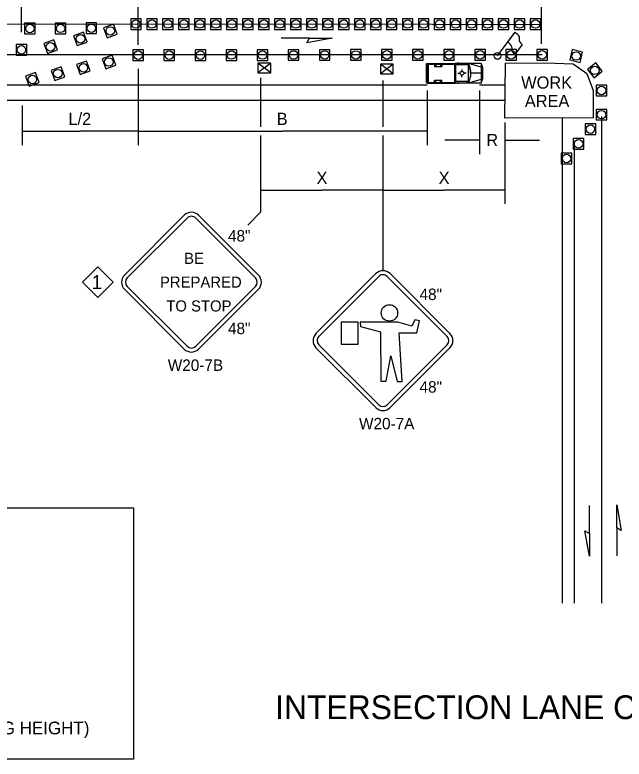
# Model space of a CAD drawing. Extents: x 99988 to 100172, y 99995 to 100047.
# Drawn here: x 100003.104 to 100006.942, y 100001.199 to 100005.887 of the extents above; entities that cross this region are included whole.
import ezdxf

# ---------------------------------------------------------------- set-up
doc = ezdxf.new("R2010")
doc.units = 0
for name, color, linetype in [('Default', 7, 'Continuous'), ('Level 15', 7, 'Continuous'), ('Level 20', 7, 'Continuous'), ('SH_DE_DetailBody1Text', 7, 'Continuous'), ('SH_DE_DetailHeading1Text', 7, 'Continuous'), ('SH_GI_TrafficMvmntArrowRt1Lane', 7, 'Continuous'), ('SH_TI_SignSpacing35to70Note', 7, 'Continuous'), ('TR_SN_WarningSigns', 7, 'Continuous'), ('TR_WZ_FlaggingStation', 7, 'Continuous'), ('TR_WZ_TrafficSafetyCone', 7, 'Continuous'), ('TR_WZ_TruckBuffer', 7, 'Continuous'), ('TR_WZ_WorkZoneDetails', 7, 'Continuous')]:
    doc.layers.add(name, color=color, linetype=linetype)

msp = doc.modelspace()

# ---------------------------------------------------------------- linework, layer by layer
at = {"layer": 'Default'}
for p, q in [((100005.7349, 100005.8272), (100001.0926, 100005.8307)), ((100005.7349, 100005.8272), (100006.4173, 100005.8296)), ((100004.7155, 100005.5226), (100004.6357, 100005.5824)), ((100004.7155, 100005.5824), (100004.6357, 100005.5226)), ((100004.6756, 100005.5525), (100004.6756, 100005.5525)), ((100004.6758, 100005.5524), (100004.6758, 100005.5524)), ((100005.4879, 100005.5169), (100005.4081, 100005.5767)), ((100005.4879, 100005.5767), (100005.4081, 100005.5169)), ((100005.448, 100005.5468), (100005.448, 100005.5468)), ((100005.4482, 100005.5467), (100005.4482, 100005.5467))]:
    msp.add_line(p, q, dxfattribs=at)
for points in [[(100004.7155, 100005.5226), (100004.7155, 100005.5824), (100004.6357, 100005.5824), (100004.6357, 100005.5226)], [(100005.4879, 100005.5169), (100005.4879, 100005.5767), (100005.4081, 100005.5767), (100005.4081, 100005.5169)], [(100006.1943, 100005.5829), (100006.4462, 100005.5845), (100006.6221, 100005.5781), (100006.7076, 100005.5179), (100006.7472, 100005.4101), (100006.7472, 100005.239), (100006.1896, 100005.2358)]]:
    msp.add_lwpolyline(points, close=True, dxfattribs=at)
at = {"layer": 'Level 15'}
for p, q in [((100003.1499, 100005.1555), (100003.515, 100005.1555)), ((100003.88, 100005.1555), (100003.515, 100005.1555)), ((100003.88, 100005.1555), (100004.7908, 100005.1555)), ((100005.7015, 100005.1555), (100004.7908, 100005.1555)), ((100006.032, 100005.0989), (100005.812, 100005.0989)), ((100006.19, 100005.0989), (100006.41, 100005.0989)), ((100004.6514, 100004.7836), (100005.0371, 100004.7836)), ((100005.4228, 100004.7836), (100005.0371, 100004.7836)), ((100005.4228, 100004.7836), (100005.8064, 100004.7836)), ((100006.19, 100004.7836), (100005.8064, 100004.7836))]:
    msp.add_line(p, q, dxfattribs=at)
at = {"layer": 'SH_DE_DetailBody1Text'}
msp.add_lwpolyline([(100003.6269, 100004.3002), (100003.7234, 100004.2037), (100003.6269, 100004.1071), (100003.5303, 100004.2037)], close=True, dxfattribs=at)
at = {"layer": 'SH_GI_TrafficMvmntArrowRt1Lane'}
for p, q in [((100004.9592, 100005.7403), (100004.7824, 100005.7403)), ((100006.7234, 100002.6206), (100006.7234, 100002.7974)), ((100006.8951, 100002.656), (100006.8951, 100002.4792))]:
    msp.add_line(p, q, dxfattribs=at)
for points in [[(100005.1034, 100005.7403), (100004.9429, 100005.712), (100004.9592, 100005.7403)], [(100006.8951, 100002.8001), (100006.9234, 100002.6396), (100006.8951, 100002.656)], [(100006.7234, 100002.4765), (100006.6951, 100002.6369), (100006.7234, 100002.6206)]]:
    msp.add_lwpolyline(points, close=True, dxfattribs=at)
at = {"layer": 'SH_TI_SignSpacing35to70Note'}
msp.add_lwpolyline([(100000.1818, 100002.782), (100003.8506, 100002.782), (100003.8506, 100001.1987), (100000.1818, 100001.1987)], close=True, dxfattribs=at)
at = {"layer": 'TR_SN_WarningSigns'}
for p, q in [((100003.7944, 100004.2485), (100004.1714, 100004.6255)), ((100004.2611, 100004.6255), (100004.638, 100004.2485)), ((100003.8124, 100004.2306), (100004.1893, 100004.6075)), ((100004.2432, 100004.6075), (100004.6201, 100004.2306)), ((100005.001, 100003.8802), (100005.3779, 100004.2572)), ((100005.0189, 100003.8623), (100005.3959, 100004.2392)), ((100005.4497, 100004.2392), (100005.8267, 100003.8623)), ((100005.4677, 100004.2572), (100005.8446, 100003.8802)), ((100004.1714, 100003.7819), (100003.7944, 100004.1588)), ((100004.1893, 100003.7998), (100003.8124, 100004.1767)), ((100004.6201, 100004.1767), (100004.2431, 100003.7998)), ((100004.638, 100004.1588), (100004.2611, 100003.7819)), ((100005.3779, 100003.4135), (100005.001, 100003.7905)), ((100005.3959, 100003.4315), (100005.0189, 100003.8084)), ((100005.8267, 100003.8084), (100005.4497, 100003.4315)), ((100005.8446, 100003.7905), (100005.4677, 100003.4135))]:
    msp.add_line(p, q, dxfattribs=at)
for points in [[(100005.2799, 100003.9511), (100005.2815, 100003.9246), (100005.4068, 100003.8917), (100005.4095, 100003.5789), (100005.4421, 100003.5789), (100005.4731, 100003.74), (100005.5122, 100003.5785), (100005.5437, 100003.5785), (100005.5258, 100003.8854), (100005.637, 100003.8854), (100005.6521, 100003.9599), (100005.6239, 100003.9653), (100005.6058, 100003.9272), (100005.5173, 100003.9511)], [(100005.1603, 100003.9508), (100005.1603, 100003.8136), (100005.2673, 100003.8136), (100005.2673, 100003.9508)]]:
    msp.add_lwpolyline(points, close=True, dxfattribs=at)
msp.add_circle((100005.4636, 100004.0099), 0.0519, dxfattribs=at)
for centre, radius, start, end in [((100004.2162, 100004.5806), 0.0635, 44.9963, 134.9997), ((100004.2162, 100004.5806), 0.0381, 44.9963, 134.9997), ((100003.8393, 100004.2037), 0.0635, 134.9966, 224.9936), ((100004.5932, 100004.2037), 0.0635, 314.9994, 44.9948), ((100005.4228, 100004.2123), 0.0635, 44.9963, 134.9997), ((100005.4228, 100004.2123), 0.0381, 44.9963, 134.9997), ((100003.8393, 100004.2037), 0.0381, 134.9966, 224.9936), ((100004.5932, 100004.2037), 0.0381, 314.9994, 44.9948), ((100005.0458, 100003.8354), 0.0635, 134.9966, 224.9936), ((100005.0458, 100003.8354), 0.0381, 134.9966, 224.9936), ((100005.7997, 100003.8353), 0.0381, 314.9994, 44.9948), ((100005.7997, 100003.8353), 0.0635, 314.9994, 44.9948), ((100004.2162, 100003.8267), 0.0635, 225, 314.9996), ((100004.2162, 100003.8267), 0.0381, 225, 314.9996), ((100005.4228, 100003.4584), 0.0635, 225, 314.9996), ((100005.4228, 100003.4584), 0.0381, 225, 314.9996)]:
    msp.add_arc(centre, radius, start, end, dxfattribs=at)
at = {"layer": 'TR_WZ_FlaggingStation'}
for p, q in [((100006.1445, 100005.629), (100006.2555, 100005.779)), ((100006.2104, 100005.7181), (100006.2556, 100005.7791)), ((100006.2104, 100005.7181), (100006.2104, 100005.7181)), ((100006.3007, 100005.7014), (100006.2544, 100005.6389))]:
    msp.add_line(p, q, dxfattribs=at)
for points in [[(100006.2556, 100005.7791), (100006.2585, 100005.7765), (100006.2676, 100005.7687), (100006.2741, 100005.7617), (100006.2776, 100005.755), (100006.2809, 100005.7495), (100006.2819, 100005.7438), (100006.2817, 100005.7379), (100006.28, 100005.7342), (100006.28, 100005.7271), (100006.2838, 100005.7193), (100006.2891, 100005.7122), (100006.3007, 100005.7014)], [(100006.2544, 100005.6389), (100006.2502, 100005.6424), (100006.2416, 100005.6508), (100006.2361, 100005.662), (100006.2359, 100005.6702), (100006.2371, 100005.6774), (100006.2355, 100005.6866), (100006.2313, 100005.6938), (100006.2237, 100005.7035), (100006.2104, 100005.7181)]]:
    msp.add_lwpolyline(points, dxfattribs=at)
msp.add_circle((100006.1445, 100005.629), 0.0214, dxfattribs=at)
at = {"layer": 'TR_WZ_TrafficSafetyCone'}
for points in [[(100003.1656, 100005.7682), (100003.2324, 100005.7682), (100003.2324, 100005.835), (100003.1656, 100005.835)], [(100003.359, 100005.769), (100003.4258, 100005.769), (100003.4258, 100005.8358), (100003.359, 100005.8358)], [(100003.5524, 100005.7698), (100003.6193, 100005.7698), (100003.6193, 100005.8366), (100003.5524, 100005.8366)], [(100003.8337, 100005.7962), (100003.9005, 100005.7962), (100003.9005, 100005.863), (100003.8337, 100005.863)], [(100003.9344, 100005.7962), (100004.0012, 100005.7962), (100004.0012, 100005.863), (100003.9344, 100005.863)], [(100004.0351, 100005.7962), (100004.1019, 100005.7962), (100004.1019, 100005.863), (100004.0351, 100005.863)], [(100004.1357, 100005.7962), (100004.2026, 100005.7962), (100004.2026, 100005.863), (100004.1357, 100005.863)], [(100004.2364, 100005.7962), (100004.3032, 100005.7962), (100004.3032, 100005.863), (100004.2364, 100005.863)], [(100004.3371, 100005.7962), (100004.4039, 100005.7962), (100004.4039, 100005.863), (100004.3371, 100005.863)], [(100004.4378, 100005.7962), (100004.5046, 100005.7962), (100004.5046, 100005.863), (100004.4378, 100005.863)], [(100004.5384, 100005.7962), (100004.6052, 100005.7962), (100004.6052, 100005.863), (100004.5384, 100005.863)], [(100004.6391, 100005.7962), (100004.7059, 100005.7962), (100004.7059, 100005.863), (100004.6391, 100005.863)], [(100004.7398, 100005.7962), (100004.8066, 100005.7962), (100004.8066, 100005.863), (100004.7398, 100005.863)], [(100004.8404, 100005.7962), (100004.9072, 100005.7962), (100004.9072, 100005.863), (100004.8404, 100005.863)], [(100004.9411, 100005.7962), (100005.0079, 100005.7962), (100005.0079, 100005.863), (100004.9411, 100005.863)], [(100005.0418, 100005.7962), (100005.1086, 100005.7962), (100005.1086, 100005.863), (100005.0418, 100005.863)], [(100005.1424, 100005.7962), (100005.2092, 100005.7962), (100005.2092, 100005.863), (100005.1424, 100005.863)], [(100005.2431, 100005.7962), (100005.3099, 100005.7962), (100005.3099, 100005.863), (100005.2431, 100005.863)], [(100005.3438, 100005.7962), (100005.4106, 100005.7962), (100005.4106, 100005.863), (100005.3438, 100005.863)], [(100005.4444, 100005.7962), (100005.5113, 100005.7962), (100005.5113, 100005.863), (100005.4444, 100005.863)], [(100005.5451, 100005.7962), (100005.6119, 100005.7962), (100005.6119, 100005.863), (100005.5451, 100005.863)], [(100005.6458, 100005.7962), (100005.7126, 100005.7962), (100005.7126, 100005.863), (100005.6458, 100005.863)], [(100005.7465, 100005.7962), (100005.8133, 100005.7962), (100005.8133, 100005.863), (100005.7465, 100005.863)], [(100005.8471, 100005.7962), (100005.9139, 100005.7962), (100005.9139, 100005.863), (100005.8471, 100005.863)], [(100005.9478, 100005.7962), (100006.0146, 100005.7962), (100006.0146, 100005.863), (100005.9478, 100005.863)], [(100006.0485, 100005.7962), (100006.1153, 100005.7962), (100006.1153, 100005.863), (100006.0485, 100005.863)], [(100006.1491, 100005.7962), (100006.2159, 100005.7962), (100006.2159, 100005.863), (100006.1491, 100005.863)], [(100006.2498, 100005.7962), (100006.3166, 100005.7962), (100006.3166, 100005.863), (100006.2498, 100005.863)], [(100006.3505, 100005.7962), (100006.4173, 100005.7962), (100006.4173, 100005.863), (100006.3505, 100005.863)], [(100003.6854, 100005.7436), (100003.7482, 100005.7665), (100003.7254, 100005.8292), (100003.6626, 100005.8064)], [(100003.4972, 100005.6937), (100003.5599, 100005.7165), (100003.5371, 100005.7793), (100003.4743, 100005.7565)], [(100003.1117, 100005.6342), (100003.1785, 100005.6342), (100003.1785, 100005.701), (100003.1117, 100005.701)], [(100003.3089, 100005.6438), (100003.3717, 100005.6666), (100003.3488, 100005.7294), (100003.286, 100005.7066)], [(100003.8478, 100005.6003), (100003.9146, 100005.6003), (100003.9146, 100005.6671), (100003.8478, 100005.6671)], [(100004.0435, 100005.6005), (100004.1104, 100005.6005), (100004.1104, 100005.6673), (100004.0435, 100005.6673)], [(100004.2393, 100005.6007), (100004.3061, 100005.6007), (100004.3061, 100005.6675), (100004.2393, 100005.6675)], [(100004.4351, 100005.6009), (100004.5019, 100005.6009), (100004.5019, 100005.6677), (100004.4351, 100005.6677)], [(100004.6309, 100005.6011), (100004.6977, 100005.6011), (100004.6977, 100005.6679), (100004.6309, 100005.6679)], [(100004.8266, 100005.6013), (100004.8934, 100005.6013), (100004.8934, 100005.6681), (100004.8266, 100005.6681)], [(100005.0224, 100005.6015), (100005.0892, 100005.6015), (100005.0892, 100005.6683), (100005.0224, 100005.6683)], [(100005.2182, 100005.6017), (100005.285, 100005.6017), (100005.285, 100005.6685), (100005.2182, 100005.6685)], [(100005.414, 100005.6019), (100005.4808, 100005.6019), (100005.4808, 100005.6687), (100005.414, 100005.6687)], [(100005.6097, 100005.6021), (100005.6765, 100005.6021), (100005.6765, 100005.6689), (100005.6097, 100005.6689)], [(100005.8055, 100005.6023), (100005.8723, 100005.6023), (100005.8723, 100005.6691), (100005.8055, 100005.6691)], [(100006.0013, 100005.6025), (100006.0681, 100005.6025), (100006.0681, 100005.6693), (100006.0013, 100005.6693)], [(100006.197, 100005.6027), (100006.2639, 100005.6027), (100006.2639, 100005.6695), (100006.197, 100005.6695)], [(100006.3928, 100005.6029), (100006.4596, 100005.6029), (100006.4596, 100005.6697), (100006.3928, 100005.6697)], [(100006.5994, 100005.6036), (100006.6643, 100005.5881), (100006.6798, 100005.6531), (100006.6149, 100005.6686)], [(100003.5157, 100005.5111), (100003.5785, 100005.534), (100003.5557, 100005.5968), (100003.4929, 100005.5739)], [(100003.6763, 100005.5477), (100003.7391, 100005.5706), (100003.7163, 100005.6334), (100003.6535, 100005.6105)], [(100003.3551, 100005.4746), (100003.4179, 100005.4974), (100003.3951, 100005.5602), (100003.3323, 100005.5373)], [(100006.7109, 100005.5434), (100006.7524, 100005.4911), (100006.8048, 100005.5326), (100006.7632, 100005.5849)], [(100003.1945, 100005.438), (100003.2573, 100005.4608), (100003.2345, 100005.5236), (100003.1717, 100005.5007)], [(100006.7665, 100005.3777), (100006.8333, 100005.3777), (100006.8333, 100005.4445), (100006.7665, 100005.4445)], [(100006.7665, 100005.2254), (100006.8333, 100005.2254), (100006.8333, 100005.2922), (100006.7665, 100005.2922)], [(100006.6962, 100005.1341), (100006.763, 100005.1341), (100006.763, 100005.2009), (100006.6962, 100005.2009)], [(100006.6213, 100005.0412), (100006.6881, 100005.0412), (100006.6881, 100005.108), (100006.6213, 100005.108)], [(100006.5464, 100004.9491), (100006.6133, 100004.9491), (100006.6133, 100005.0159), (100006.5464, 100005.0159)]]:
    msp.add_lwpolyline(points, close=True, dxfattribs=at)
for centre in [(100003.8671, 100005.8296), (100003.9678, 100005.8296), (100004.0685, 100005.8296), (100004.1692, 100005.8296), (100004.2698, 100005.8296), (100004.3705, 100005.8296), (100004.4712, 100005.8296), (100004.5718, 100005.8296), (100004.6725, 100005.8296), (100004.7732, 100005.8296), (100004.8738, 100005.8296), (100004.9745, 100005.8296), (100005.0752, 100005.8296), (100005.1758, 100005.8296), (100005.2765, 100005.8296), (100005.3772, 100005.8296), (100005.4778, 100005.8296), (100005.5785, 100005.8296), (100005.6792, 100005.8296), (100005.7799, 100005.8296), (100005.8805, 100005.8296), (100005.9812, 100005.8296), (100006.0819, 100005.8296), (100006.1825, 100005.8296), (100006.2832, 100005.8296), (100006.3839, 100005.8296), (100003.199, 100005.8016), (100003.3924, 100005.8024), (100003.5859, 100005.8032), (100003.7054, 100005.7864), (100003.5171, 100005.7365), (100003.1451, 100005.6676), (100003.3289, 100005.6866), (100003.8812, 100005.6337), (100004.0769, 100005.6339), (100004.2727, 100005.6341), (100004.4685, 100005.6343), (100004.6643, 100005.6345), (100004.86, 100005.6347), (100005.0558, 100005.6349), (100005.2516, 100005.6351), (100005.4474, 100005.6353), (100005.6431, 100005.6355), (100005.8389, 100005.6357), (100006.0347, 100005.6359), (100006.2305, 100005.6361), (100006.4262, 100005.6363), (100006.6396, 100005.6284), (100003.6963, 100005.5906), (100003.5357, 100005.554), (100006.7578, 100005.538), (100003.2145, 100005.4808), (100003.3751, 100005.5174), (100006.7999, 100005.4111), (100006.7999, 100005.2588), (100006.7296, 100005.1675), (100006.6547, 100005.0746), (100006.5799, 100004.9825)]:
    msp.add_circle(centre, 0.0268, dxfattribs=at)
at = {"layer": 'TR_WZ_TruckBuffer'}
for p, q in [((100005.6946, 100005.5763), (100005.6946, 100005.4634)), ((100005.6984, 100005.5801), (100005.7022, 100005.5801)), ((100005.7022, 100005.5801), (100005.7022, 100005.4596)), ((100005.7028, 100005.5821), (100005.8779, 100005.582)), ((100005.7028, 100005.5821), (100005.7028, 100005.4576)), ((100005.7078, 100005.5771), (100005.7077, 100005.4626)), ((100005.7078, 100005.5771), (100005.873, 100005.577)), ((100005.7473, 100005.5771), (100005.7473, 100005.5628)), ((100005.7473, 100005.5628), (100005.794, 100005.5628)), ((100005.7566, 100005.5771), (100005.7566, 100005.5628)), ((100005.7856, 100005.5771), (100005.7856, 100005.5628)), ((100005.794, 100005.5771), (100005.794, 100005.5628)), ((100005.873, 100005.577), (100005.8729, 100005.4625)), ((100005.8779, 100005.582), (100005.8779, 100005.4575)), ((100005.8803, 100005.582), (100005.8802, 100005.4575)), ((100006.0411, 100005.5819), (100005.8803, 100005.582)), ((100005.9592, 100005.5723), (100005.8803, 100005.5724)), ((100005.9022, 100005.5838), (100005.8926, 100005.5838)), ((100005.9592, 100005.582), (100005.949, 100005.5723)), ((100005.9592, 100005.582), (100005.9591, 100005.4574)), ((100005.9607, 100005.582), (100005.9606, 100005.4574)), ((100006.041, 100005.5591), (100005.9607, 100005.582)), ((100006.0411, 100005.5819), (100006.041, 100005.4574)), ((100006.0411, 100005.5819), (100006.0489, 100005.5568)), ((100006.0489, 100005.5568), (100006.0489, 100005.4825)), ((100005.6946, 100005.5286), (100005.7022, 100005.5263)), ((100005.6946, 100005.5111), (100005.7022, 100005.5134)), ((100005.6967, 100005.5199), (100005.7002, 100005.5199)), ((100005.6984, 100005.5216), (100005.6984, 100005.5181)), ((100005.8943, 100005.5193), (100005.907, 100005.5195)), ((100005.9086, 100005.5195), (100005.9086, 100005.5195)), ((100005.92, 100005.4958), (100005.9202, 100005.5051)), ((100005.9206, 100005.5444), (100005.9206, 100005.5343)), ((100005.9462, 100005.5198), (100005.9355, 100005.5198)), ((100006.041, 100005.5197), (100005.9764, 100005.5197)), ((100005.6984, 100005.4596), (100005.7022, 100005.4596)), ((100005.7028, 100005.4576), (100005.8779, 100005.4575)), ((100005.7077, 100005.4626), (100005.8729, 100005.4625)), ((100005.7472, 100005.4625), (100005.7472, 100005.4769)), ((100005.7472, 100005.4769), (100005.794, 100005.4768)), ((100005.7566, 100005.4625), (100005.7566, 100005.4768)), ((100005.7855, 100005.4625), (100005.7855, 100005.4768)), ((100005.794, 100005.4625), (100005.794, 100005.4768)), ((100005.9591, 100005.4671), (100005.8802, 100005.4671)), ((100006.041, 100005.4574), (100005.8802, 100005.4575)), ((100005.9507, 100005.4671), (100005.9591, 100005.4574)), ((100006.041, 100005.4802), (100005.9606, 100005.4574)), ((100006.041, 100005.4574), (100006.0489, 100005.4825)), ((100005.9021, 100005.4557), (100005.8925, 100005.4557))]:
    msp.add_line(p, q, dxfattribs=at)
for centre, radius in [((100005.6984, 100005.5199), 0.00175), ((100005.9206, 100005.5197), 0.012)]:
    msp.add_circle(centre, radius, dxfattribs=at)
for centre, radius, start, end in [((100005.6984, 100005.5763), 0.0038, 89.9656, 179.9656), ((100005.8457, 100005.5198), 0.1307, 331.5161, 28.4256), ((100005.6984, 100005.4634), 0.0038, 179.9656, 269.9656)]:
    msp.add_arc(centre, radius, start, end, dxfattribs=at)
at = {"layer": 'TR_WZ_WorkZoneDetails'}
for p, q in [((100003.1451, 100005.7776), (100003.1451, 100006.3559)), ((100003.8812, 100005.6997), (100003.8812, 100006.3559)), ((100006.4214, 100005.7046), (100006.4214, 100006.3559)), ((100001.0926, 100005.6386), (100006.4262, 100005.6386)), ((100003.88, 100005.5486), (100003.88, 100005.0675)), ((100004.6514, 100005.4912), (100004.6514, 100005.183)), ((100005.4228, 100005.4734), (100005.4228, 100005.183)), ((100002.281, 100005.4465), (100005.7015, 100005.4465)), ((100005.7015, 100005.411), (100005.7015, 100005.0675)), ((100006.032, 100005.4465), (100006.1939, 100005.4465)), ((100006.032, 100005.411), (100006.032, 100005.0109)), ((100002.281, 100005.3505), (100006.1907, 100005.3505)), ((100003.1499, 100005.3156), (100003.1499, 100005.0675)), ((100006.5524, 100005.2365), (100006.5524, 100002.1809)), ((100006.8001, 100005.2483), (100006.8001, 100002.1809)), ((100006.19, 100005.2089), (100006.19, 100004.6978)), ((100004.6514, 100005.128), (100004.6514, 100004.645)), ((100005.4228, 100005.128), (100005.4228, 100004.2758)), ((100006.6267, 100005.0846), (100006.6267, 100002.1809)), ((100004.6514, 100004.645), (100004.5707, 100004.5618))]:
    msp.add_line(p, q, dxfattribs=at)

# ---------------------------------------------------------------- texts
at = {"layer": 'Level 20'}
for s, p in [('L/2', (100003.4416, 100005.194)), ('B', (100004.7537, 100005.194)), ('R', (100006.074, 100005.0604)), ('X', (100005.0044, 100004.8221)), ('X', (100005.7737, 100004.8221))]:
    msp.add_text(s, height=0.077, rotation=360, dxfattribs=at).set_placement(p)
at = {"layer": 'SH_DE_DetailBody1Text'}
for s, height, p in [('WORK', 0.077, (100006.2938, 100005.4227)), ('AREA', 0.077, (100006.3166, 100005.3066)), ('1', 0.088, (100003.5883, 100004.1597)), ("TEMPORARY SIGN LOCATION (5' MOUNTING HEIGHT)", 0.08, (100000.8016, 100001.3549))]:
    msp.add_text(s, height=height, dxfattribs=at).set_placement(p)
at = {"layer": 'SH_DE_DetailHeading1Text'}
msp.add_text('INTERSECTION LANE CLOSURE - THREE LANE ROADWAY', height=0.15, dxfattribs=at).set_placement((100004.7438, 100001.4505))
at = {"layer": 'TR_SN_WarningSigns'}
for s, height, p in [('48"', 0.07219, (100004.4468, 100004.4592)), ('BE', 0.06996, (100004.1704, 100004.3186)), ('PREPARED', 0.06996, (100004.0183, 100004.1687)), ('48"', 0.07219, (100005.6534, 100004.0909)), ('TO STOP', 0.06996, (100004.0581, 100004.0188)), ('48"', 0.07219, (100004.4468, 100003.8759)), ('W20-7B', 0.07219, (100004.0675, 100003.6447)), ('48"', 0.07219, (100005.6534, 100003.5076)), ('W20-7A', 0.07219, (100005.2723, 100003.2763))]:
    msp.add_text(s, height=height, dxfattribs=at).set_placement(p)

doc.saveas('drawing.dxf')
